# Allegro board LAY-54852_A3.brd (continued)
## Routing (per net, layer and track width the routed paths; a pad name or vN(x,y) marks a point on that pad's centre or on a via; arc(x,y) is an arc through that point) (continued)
FRS_EN: length 14.3
  TOP w0.091: U401.1 v1(36.37,16.38)
  TOP w0.203: v1(25.09,15.95) 25.12,15.95 25.33,16.15 U402.B6
  BOTTOM w0.091: v1(25.09,15.95) 25.09,15.78 26.17,14.7 31.07,14.7 33.6,17.23 35.51,17.23 v1(36.37,16.38)
FT_BMODE_DIR: length 16
  TOP w0.091: U1409.14 v1(18.45,57.25) ; v1(21.46,60) 22.14,60.68 24.49,60.68 25.91,59.26 R1728.1 27.76,59.87 29.1,61.21 U1404.5 29.1,62 U1404.4
  BOTTOM w0.091: v1(18.45,57.25) 18.45,58.23 20.22,60 v1(21.46,60)
FT_BOOT_MODE0: length 7.1
  TOP w0.091: U1409.1 24.26,55.25 26.01,57 27.77,57 28.86,58.09 R1731.1
FT_BOOT_MODE1: length 8.4
  TOP w0.091: v1(27.57,57.37) 26.08,57.37 24.45,55.75 U1409.2 ; v1(29.78,57.24) 29.78,57.25 R1732.1
  BOTTOM w0.091: v1(27.57,57.37) 27.7,57.24 v1(29.78,57.24)
FT_BOOT_MODE2: length 9.2
  TOP w0.091: R1418.1 30.75,58.31 v1(30.75,57.62) ; U1409.3 24.64,56.25 26.14,57.75 27.77,57.75 v1(27.97,57.95)
  BOTTOM w0.091: v1(27.97,57.95) 30.41,57.95 v1(30.75,57.62)
FT_BOOT_MODE3: length 10.1
  TOP w0.091: R1419.1 31.36,58.01 v1(31.36,57.61) ; v1(26.64,58.13) 26.21,58.13 24.84,56.75 U1409.4
  BOTTOM w0.091: v1(26.64,58.13) 26.84,58.33 30.63,58.33 v1(31.36,57.61)
FT_EECLK: length 20
  TOP w0.091: v1(3.79,35.78) 3.25,35.78 1.56,37.47 R1428.2 ; U1706.62 v1(8,24.87)
  BOTTOM w0.091: v1(3.79,35.78) 4.85,34.71 4.85,33.41 7.05,31.2 7.05,25.81 v1(8,24.87)
FT_EECS: length 19.4
  TOP w0.091: v1(5.57,35.63) 4.93,36.26 R1740.2 ; v1(8.53,24.89) 8.53,24.71 8.19,24.37 U1706.63
  BOTTOM w0.091: v1(8.53,24.89) 7.37,26.05 7.37,31.2 5.57,33 v1(5.57,35.63)
FT_EEDATA: length 28
  TOP w0.091: v1(8.58,25.66) 8.29,25.37 U1706.61 ; v1(4.22,47.2) 2.94,47.2 R1739.2
  BOTTOM w0.091: v1(4.22,47.2) 4.9,46.53 4.9,41.95 5.94,40.9 5.94,32.93 7.67,31.21 7.67,26.56 v1(8.58,25.66)
FT_IO_NINT1: length 25.1
  TOP w0.091: v1(18.19,30.39) 18.17,30.37 U1706.30 ; R1487.1 v1(21.61,51.73)
  BOTTOM w0.091: v1(21.61,51.73) 21.61,45.93 18.14,42.46 18.14,37.56 17.5,36.92 17.5,31.09 v1(18.19,30.39)
FT_IOEXP2_SCL: length 4.1
  TOP w0.091: U1409.19 17.94,54.54 16.9,53.5 R1470.2
FT_IOEXP2_SDA: length 4.1
  TOP w0.091: U1409.20 20.46,54.17 20.25,53.97 17.99,53.97 17.81,53.79 17.81,53.2 R1469.2
FT_NPWREN: length 62.9
  TOP w0.091: v1(6.07,62.71) 6.17,62.82 11.01,62.82 12.67,64.47 17.59,64.47 19.04,65.93 R1749.1 ; R1464.1 6.13,49.4 v1(6.13,48.87) ; v1(8.53,26.24) 8.17,25.87 U1706.60 4.53,25.87 3.8,25.14 3.8,24.75 2.1,23.06 TP1407.1
  BOTTOM w0.091: v1(6.07,62.71) 5.33,61.98 5.33,49.66 v1(6.13,48.87) 6.13,46.96 6.67,46.42 6.67,33.48 8.53,31.61 v1(8.53,26.24)
FT_NSUSPEND: length 36.1
  TOP w0.091: R1744.1 v1(13.36,65.81) ; v1(14.51,37.34) 14.51,37.05 TP1408.1 13.5,36.04 U1706.36
  BOTTOM w0.091: v1(13.36,65.81) 13.14,66.03 12.4,66.03 11.87,65.49 11.87,60.46 13.49,58.84 13.49,41.07 14.51,40.04 v1(14.51,37.34)
FT_ONOFF: length 8.6
  TOP w0.091: U1409.12 18.06,58.46 16.91,59.6 16.91,61.49 17.21,61.79 U1406.3 19.25,61.79 R1746.1
FT_OSCI: length 8.9
  TOP w0.091: X1401.1 3.94,18 3.94,19.17 4.52,19.75 4.52,19.84 C1428.1 4.7,20.63 5.03,20.96 7.91,20.96 8,21.05 U1706.2
FT_OSCO: length 6.4
  TOP w0.091: X1401.3 5.39,18.95 C1430.1 5.39,20.61 5.51,20.73 8.1,20.73 8.5,21.13 U1706.3
FT_POR_B: length 13.5
  TOP w0.091: R1747.1 13.94,61.79 U1406.6 16.09,61.79 17.45,63.15 20.77,63.15 21.62,62.3 21.62,61.08 20.96,60.41 U1409.10
FT_RC_SEL: length 15.4
  TOP w0.091: U1409.13 17.73,57.75 16.76,58.73 v1(16.21,58.73) ; v1(15.67,69.68) 15.77,69.79 R1751.1
  BOTTOM w0.091: v1(15.67,69.68) 16.21,69.14 v1(16.21,58.73)
FT_SCL: length 29.4
  TOP w0.091: TP1912.1 19,27.73 18.8,27.92 R1726.1 18.45,28.3 18.38,28.37 v1(18.21,28.37) U1706.26 ; R1470.1 16.9,52.06 v1(17.36,51.6)
  BOTTOM w0.091: v1(17.36,51.6) 17.58,51.38 17.58,38.25 16.43,37.1 16.43,30.15 v1(18.21,28.37)
FT_SD_CD: length 181.7
  TOP w0.091: U1409.16 18.56,56.25 v1(18.5,56.31) ; U1707.1 134.76,42.76 135,43 v1(135,43.69) R1053.2
  BOTTOM w0.091: v1(135,43.69) 134.92,43.69 133.16,45.45 133.16,69.97 133.34,70.15 133.34,76.85 125.88,84.31 21.49,84.31 18.08,80.89 18.08,56.74 v1(18.5,56.31)
FT_SD_PWREN: length 182.5
  TOP w0.091: U1409.15 18.18,56.75 v1(17.64,57.29) ; R1057.1 137.37,44.31 R1056.2 v1(136.15,43.67)
  BOTTOM w0.091: v1(136.15,43.67) 133.38,46.44 133.38,69.88 133.56,70.06 133.56,76.94 125.97,84.53 21.22,84.53 17.57,80.88 17.57,57.36 v1(17.64,57.29)
FT_SDA: length 29.3
  TOP w0.091: v1(18.18,29.37) 18.43,29.37 18.44,29.38 R1727.1 18.79,29.2 19.07,28.92 20.5,28.92 TP1913.1 ; v1(18.18,29.37) 18.18,28.96 18.09,28.87 U1706.27 ; v1(18.18,29.37) U1706.28 ; R1469.1 18.08,51.76 v1(17.9,51.58)
  BOTTOM w0.091: v1(18.18,29.37) 16.96,30.59 16.96,36.69 17.9,37.63 v1(17.9,51.58)
FT_SYS_NRST: length 3.9
  TOP w0.091: U1406.1 19.14,60.79 R1745.1 19.79,59.35 20.46,58.69 U1409.11
FT_TST0: length 43.7
  TOP w0.091: U1706.21 17.84,25.87 v1(18.03,26.05) ; R1455.1 v1(9.3,64.08)
  BOTTOM w0.091: v1(18.03,26.05) 17.74,26.05 15.64,28.15 15.64,33.72 11.65,37.71 11.65,55.89 9.3,58.24 v1(9.3,64.08)
FT_TST1: length 41.1
  TOP w0.091: v1(18.01,26.59) 17.8,26.37 U1706.22 ; v1(24.41,61.31) 24.69,61.59 R1457.1
  BOTTOM w0.091: v1(18.01,26.59) 18.67,27.24 18.67,41.35 23.07,45.76 23.07,59.97 v1(24.41,61.31)
FT_TST2: length 8
  TOP w0.091: R1456.1 17.69,22.87 16.04,22.87 15.64,23.27 15.64,26.46 16.04,26.87 U1706.23
FT_TST3: length 40.7
  TOP w0.091: U1706.24 v1(11.06,27.37) ; R1458.1 6.47,57.8 7.23,57.04 7.23,55.91 5.42,54.1 5.42,52.5 5.73,52.19 5.73,50.84 6.75,49.81 v1(6.75,48.82)
  BOTTOM w0.091: v1(11.06,27.37) 9.36,29.07 9.36,44.68 6.75,47.28 v1(6.75,48.82)
FT_USB_DN: length 16.7
  TOP w0.102: U1403.C1 15.52,9.92 15.52,10.79 15.64,10.91 v1(15.64,10.97) ; U1706.7 10.5,21.01 10.65,20.86 10.65,16.42 14.39,12.68 14.39,12.45 v1(14.39,12.44)
  BOTTOM w0.102: v1(15.64,10.97) 15.64,10.91 15.52,10.79 15.52,10.28 15.17,9.94 14.7,9.94 14.1,10.54 14.1,11.46 14.39,11.76 v1(14.39,12.44)
FT_USB_DP: length 16.6
  TOP w0.102: U1403.C2 15.1,9.93 15.31,10.13 15.31,10.79 v1(15.06,11.03) ; v1(14.95,12.4) 14.95,12.42 10.86,16.51 10.86,20.86 11,21.01 U1706.8
  BOTTOM w0.102: v1(14.95,12.4) 14.89,12.4 14.61,12.12 14.61,11.67 14.31,11.37 14.31,10.63 14.79,10.15 15.08,10.15 15.31,10.37 15.31,10.79 v1(15.06,11.03)
FTA_TCK: length 20.7
  TOP w0.091: v1(16.93,21.86) 16.92,21.84 U1706.16 ; U1408.2 21.85,37.79 21.06,37 21.06,27.27 20.35,26.56 v1(19.94,26.56)
  BOTTOM w0.091: v1(16.93,21.86) 16.93,23.61 19.89,26.56 v1(19.94,26.56)
FTA_TDI: length 17.7
  TOP w0.091: U1706.17 18.82,23.87 20.08,25.13 20.08,25.98 21.28,27.18 21.28,36.65 22.25,37.62 U1408.3
FTA_TDO: length 18.6
  TOP w0.091: U1706.18 v1(18.22,24.37) ; U1408.5 23.05,37.55 21.71,36.22 21.71,27 20.54,25.82 20.54,24.68 v1(19.92,24.06)
  BOTTOM w0.091: v1(18.22,24.37) 19.6,24.37 v1(19.92,24.06)
FTA_TMS: length 22.3
  TOP w0.091: U1706.19 15.96,24.87 15.85,24.76 15.85,23.36 16.13,23.09 18.35,23.09 20.3,25.04 20.3,25.89 21.49,27.09 21.49,36.31 22.65,37.46 U1408.4
FTC_RXD: length 17.5
  TOP w0.091: R1819.1 8.51,44.55 7.98,44.02 7.13,44.02 6.95,43.84 D1404.C 7.98,41.99 7.98,39.6 8.95,38.64 11.72,38.64 12.83,37.53 12.83,35.83 12,35.01 U1706.39
FTC_TXD: length 15.2
  TOP w0.091: R1817.1 11.73,44.27 12.17,44.27 12.58,43.86 D1403.C 11.7,43.37 11.22,42.88 11.22,39.5 13.21,37.51 13.21,35.43 12.5,34.73 U1706.38
FTD_CTS: length 3.5
  TOP w0.091: TP1406.1 2.39,28.87 U1706.54
FTD_RTS: length 3.6
  TOP w0.091: TP1405.1 2.53,29.37 U1706.53
FTD_RXD: length 32.9
  TOP w0.091: U1706.52 7.94,29.87 v1(8.05,29.97) ; R1820.1 6.49,45.3 6.04,44.85 v1(6.04,41.93)
  TOP w0.381: v1(4.23,50.69) 3.1,51.82 3.1,52.43 D1405.C
  BOTTOM w0.091: v1(4.23,50.69) 5.11,49.81 5.11,42.86 v1(6.04,41.93) 6.45,41.52 6.45,33.38 8.05,31.79 v1(8.05,29.97)
FTD_TXD: length 13.6
  TOP w0.091: v1(7.26,34.48) 7.5,34.24 U1706.48 ; v1(8.61,39.63) 8.61,43.15 8.92,43.47 D1406.C 9.73,44.17 9.6,44.3 R1818.1
  BOTTOM w0.091: v1(8.61,39.63) 8.61,35.89 7.26,34.55 v1(7.26,34.48)
GPIO_IO00: length 51.1
  TOP w0.081: 92.71,56.46 92.39,56.46 92.14,56.21 U101.B16
  TOP w0.091: v1(115.92,54.45) 115.77,54.45 115.08,53.75 102.5,53.75 98.58,57.68 93.93,57.68 92.71,56.46 ; R1415.2 v1(120.16,73.59) 120.16,74.11 121.21,75.16 J1401.27
  BOTTOM w0.091: v1(115.92,54.45) 115.92,54.58 118.53,57.19 118.53,69.58 119.67,70.71 119.67,73.1 v1(120.16,73.59)
GPIO_IO01: length 56.8
  TOP w0.091: U101.B17 92.83,56.21 94.09,57.46 98.49,57.46 102.41,53.54 115.54,53.54 v1(115.91,53.9) ; J1401.28 121.21,79.28 122.07,78.41 122.07,74.27 v1(121.52,73.72) 121.35,73.56 R1417.2
  BOTTOM w0.091: v1(121.52,73.72) 120.07,72.28 120.07,70.23 118.75,68.91 118.75,56.75 v1(115.91,53.9)
GPIO_IO02: length 39.5
  TOP w0.081: 92.87,55.96 92.25,55.96 U101.C16
  TOP w0.091: J1401.3 90.73,74.11 90.86,73.97 v1(90.86,73.72) R1414.2 ; 92.87,55.96 93.06,55.96 94.32,57.22 95.52,57.22 96.54,56.2 v1(96.74,56.2)
  BOTTOM w0.091: v1(96.74,56.2) 96.74,56.34 97.49,57.09 97.49,62.5 95.75,64.24 95.75,68.08 93.39,70.44 93.26,70.44 92.45,69.63 92.33,69.63 92.2,69.76 92.2,69.89 93,70.7 93,70.83 92.87,70.96 92.74,70.96 91.94,70.15 91.81,70.15 91.68,70.28 91.68,70.41 92.49,71.22 92.49,71.35 92.36,71.48 92.23,71.48 91.42,70.67 91.29,70.67 91.16,70.8 91.16,70.93 91.97,71.74 91.97,71.87 91.84,71.99 91.71,71.99 90.9,71.19 90.77,71.19 90.64,71.32 90.64,71.45 91.45,72.25 91.45,72.38 90.86,72.97 v1(90.86,73.72)
GPIO_IO03: length 38.7
  TOP w0.091: U101.C17 96.95,55.71 97.27,56.03 v1(97.27,56.19) ; R1416.2 93.27,73.24 v1(93.27,73.72) J1401.5
  BOTTOM w0.091: v1(97.27,56.19) 97.74,56.67 97.74,62.56 96.02,64.28 96.02,68.21 93.37,70.86 93.37,72.35 93.25,72.48 91.8,72.48 91.7,72.57 91.7,72.75 91.8,72.84 94.73,72.84 94.82,72.93 94.82,73.08 94.73,73.17 91.38,73.17 91.24,73.31 91.24,73.97 91.38,74.11 93.18,74.11 93.27,74.02 v1(93.27,73.72)
GPIO_IO04: length 46
  TOP w0.081: U101.D16 92.24,55.45 92.98,55.45
  TOP w0.091: 92.98,55.45 97.19,55.45 97.8,56.07 v1(97.8,56.16) ; v1(90.24,73.79) 87.98,73.79 R1429.1 ; v1(95.1,73.79) 95.81,74.5 J1401.7
  BOTTOM w0.091: v1(97.8,56.16) 97.96,56.32 97.96,62.65 96.32,64.3 96.32,68.22 93.68,70.86 93.68,71.53 93.77,71.62 95.21,71.62 95.3,71.53 95.3,70.47 95.4,70.38 95.65,70.38 95.74,70.47 95.74,71.96 95.65,72.05 93.84,72.05 93.68,72.21 93.68,72.37 93.77,72.46 95.56,72.46 95.65,72.55 95.65,72.79 95.56,72.88 95.26,72.88 95.14,73 95.14,73.2 95.27,73.33 95.56,73.33 95.65,73.42 95.65,73.7 95.56,73.79 v1(95.1,73.79) 94.49,74.4 90.85,74.4 v1(90.24,73.79)
GPIO_IO05: length 50.6
  TOP w0.091: U101.D17 100.43,55.21 102.32,53.32 115.86,53.32 v1(115.88,53.34) ; J1401.29 v1(123.75,74.22)
  BOTTOM w0.091: v1(123.75,74.22) 121.75,72.22 121.75,70.99 118.97,68.21 118.97,56.2 116.11,53.34 v1(115.88,53.34)
GPIO_IO06: length 53.8
  TOP w0.081: 92.63,54.96 92.25,54.96 U101.E16
  TOP w0.091: J1401.31 v1(126.29,74.22) ; 92.63,54.96 100.37,54.96 102.23,53.1 115.53,53.1 115.82,52.81 v1(115.94,52.81)
  BOTTOM w0.091: v1(115.94,52.81) 116.1,52.81 119.19,55.9 119.19,68.11 122.06,70.98 122.06,71.52 124.75,74.22 v1(126.29,74.22)
GPIO_IO07: length 55.1
  TOP w0.091: v1(115.92,52.21) 115.25,52.88 102.14,52.88 100.32,54.71 U101.E17 ; J1401.26 v1(118.67,79.17)
  BOTTOM w0.091: v1(115.92,52.21) 115.92,52.3 115.5,52.72 115.5,54.61 118.32,57.42 118.32,63.71 118.21,63.81 118.21,74.29 118.67,74.75 v1(118.67,79.17)
GPIO_IO08: length 49.4
  TOP w0.081: U101.K14 v1(90.99,51.71)
  TOP w0.091: v1(97.08,61.6) 103.39,55.29 105.11,55.29 105.75,55.94 106.28,55.94 106.52,55.7 107.41,55.7 107.8,56.09 v1(108.6,56.09)
  TOP w0.102: v1(110.62,73.04) 111.04,72.63 U805.2
  BOTTOM w0.091: v1(110.62,73.04) 109.64,73.04 107.72,71.13 107.72,67.1 108.07,66.75 108.07,57.34 108.6,56.81 v1(108.6,56.09) ; v1(97.08,61.6) 96.62,61.13 96.62,56.92 95.99,56.29 95.99,55.26 92.07,51.35 91.11,51.35 90.99,51.46 v1(90.99,51.71)
GPIO_IO09: length 40.1
  TOP w0.081: U101.F16 92.24,54.45 92.88,54.45
  TOP w0.091: 92.88,54.45 100.26,54.45 102.21,52.5 v1(109.21,52.5)
  TOP w0.102: U805.5 v1(109.63,72.13)
  BOTTOM w0.091: v1(109.21,52.5) 109.61,52.9 109.61,58.47 108.34,59.74 108.34,66.8 107.94,67.19 107.94,70.98 109.08,72.13 v1(109.63,72.13)
GPIO_IO10: length 38.3
  TOP w0.091: U101.F17 100.2,54.21 102.28,52.12 109.36,52.12 109.73,52.49 v1(109.74,52.49)
  TOP w0.102: U805.7 v1(109,70.81)
  BOTTOM w0.091: v1(109.74,52.49) 109.82,52.58 109.82,59.17 109.37,59.62 109.37,66.14 108.16,67.36 108.16,69.97 v1(109,70.81)
GPIO_IO11: length 40.6
  TOP w0.081: U101.G16 92.24,53.95 92.79,53.95
  TOP w0.091: v1(110.27,52.49) 110.27,52.49 109.68,51.9 102.19,51.9 100.14,53.95 92.79,53.95
  TOP w0.102: U805.10 110.64,69.6 110.19,69.14 109.3,69.14 v1(108.97,69.48)
  BOTTOM w0.091: v1(108.97,69.48) 108.59,69.48 108.38,69.27 108.38,67.53 110.37,65.54 110.37,59.04 110.04,58.72 110.04,53.06 110.27,52.83 v1(110.27,52.49)
GPIO_IO12: length 61.6
  TOP w0.081: U101.F14 v1(90.99,53.71)
  TOP w0.091: U803.2 133.17,71.1 133.59,70.68 133.59,67.24 130.53,64.17 125.52,64.17 123.41,62.06 119.18,62.06 115.8,58.67 115.8,57.63 113.23,55.07 103.31,55.07 97.21,61.17 95.39,61.17 v1(95.33,61.1)
  BOTTOM w0.081: 92.13,54.87 92.13,55.64 93.35,56.87 93.35,58.33
  BOTTOM w0.091: 93.35,58.33 93.51,58.48 93.51,59.74 94.87,61.1 v1(95.33,61.1) ; 92.13,54.87 90.99,53.74 v1(90.99,53.71)
GPIO_IO13: length 126.8
  TOP w0.091: v1(104.68,82.94) 104.68,84.14 104.89,84.35 126.71,84.35 127.7,83.35 127.7,78.89 128.83,77.77 J1401.33 128.83,74.36 129.21,73.99 129.21,70.22 v1(128.83,69.85) ; v1(127.11,60.33) 126.9,60.12 119.25,60.12 117.3,58.17 117.3,53.03 115.95,51.69 102.1,51.69 100.05,53.73 92.52,53.73 U101.G17 ; v1(77.71,82.63) 77.71,76.85 76,75.14 R1439.1
  BOTTOM w0.091: v1(128.83,69.85) 128.83,62.96 127.11,61.24 v1(127.11,60.33) ; v1(77.71,82.63) 78.03,82.94 v1(104.68,82.94)
GPIO_IO14: length 43.9
  TOP w0.081: U101.H16 92.25,53.46 92.74,53.46
  TOP w0.091: J1401.8 95.81,79.2 96.67,78.34 96.67,73.73 v1(97.08,73.32) ; v1(97.53,52.84) 96.78,52.84 96.15,53.46 92.74,53.46
  BOTTOM w0.091: v1(97.08,73.32) 96.23,73.32 96.05,73.13 96.05,70.34 97.74,68.64 97.74,66.96 97.65,66.87 96.86,66.87 96.77,66.78 96.77,66.59 96.86,66.5 97.65,66.5 97.74,66.41 97.74,66.23 97.65,66.14 96.86,66.14 96.77,66.05 96.77,65.86 96.86,65.77 97.65,65.77 97.74,65.68 97.74,65.5 97.65,65.41 96.86,65.41 96.77,65.31 96.77,65.13 96.86,65.04 97.65,65.04 97.74,64.95 97.74,64.77 97.65,64.67 96.86,64.67 96.77,64.58 96.77,64.4 96.86,64.31 97.65,64.31 97.74,64.22 97.74,63.47 98.18,63.04 98.18,53.49 v1(97.53,52.84)
GPIO_IO15: length 40.9
  TOP w0.091: U101.H17 96.1,53.21 97,52.3 v1(97.57,52.3) ; v1(97.79,73.27) 98.52,73.27 99.24,73.98 99.24,79.31 98.35,80.2 J1401.10
  BOTTOM w0.091: v1(97.79,73.27) 97.47,72.95 97.47,71.63 98.43,70.67 98.43,70.16 98.34,70.07 98.16,70.07 98.07,69.98 98.07,69.8 98.16,69.71 98.34,69.71 98.43,69.62 98.43,69.43 98.34,69.34 98.16,69.34 98.07,69.25 98.07,69.07 98.16,68.98 98.34,68.98 98.43,68.88 98.43,68.7 98.34,68.61 98.16,68.61 98.07,68.52 98.07,68.34 98.16,68.24 98.34,68.24 98.43,68.15 98.43,67.97 98.34,67.88 98.16,67.88 98.07,67.79 98.07,67.6 98.16,67.51 98.34,67.51 98.43,67.42 98.43,67.24 98.34,67.15 98.16,67.15 98.07,67.06 98.07,66.87 98.16,66.78 98.34,66.78 98.43,66.69 98.43,66.51 98.34,66.42 98.16,66.42 98.07,66.32 98.07,66.14 98.16,66.05 98.34,66.05 98.43,65.96 98.43,65.78 98.34,65.68 98.16,65.68 98.07,65.59 98.07,65.41 98.16,65.32 98.34,65.32 98.43,65.23 98.43,65.04 98.34,64.95 98.16,64.95 98.07,64.86 98.07,64.68 98.16,64.59 98.34,64.59 98.43,64.5 98.43,53.04 97.69,52.3 v1(97.57,52.3)
GPIO_IO16: length 38.5
  TOP w0.081: U101.J16 92.25,52.96 92.79,52.96
  TOP w0.091: U804.2 101.09,72.63 101.78,73.32 101.78,73.91 v1(101.58,74.11) ; 92.79,52.96 96.04,52.96 97.07,51.93 101.32,51.93 v1(101.41,51.84)
  BOTTOM w0.091: v1(101.58,74.11) 101.48,74.11 101.13,74.46 100.16,74.46 100.06,74.36 100.06,74.15 100.19,74.03 100.69,74.03 100.77,73.95 100.77,73.56 100.68,73.47 100.14,73.47 100.05,73.38 100.05,73.2 100.14,73.11 100.68,73.11 100.77,73.01 100.77,52.4 101.33,51.84 v1(101.41,51.84)
GPIO_IO17: length 38.3
  TOP w0.081: 92.7,52.45 91.74,52.45 U101.K15
  TOP w0.091: U804.5 99.53,72.13 v1(99.18,72.48) ; v1(98.02,51.33) 97.04,51.33 95.92,52.45 92.7,52.45
  BOTTOM w0.091: v1(99.18,72.48) 99.02,72.48 98.62,72.08 98.62,71.21 99.36,70.47 99.74,70.47 99.83,70.38 99.83,70.19 99.74,70.1 99.36,70.1 99.27,70.01 99.27,69.83 99.36,69.74 99.74,69.74 99.83,69.64 99.83,69.46 99.74,69.37 99.36,69.37 99.27,69.28 99.27,69.1 99.36,69 99.74,69 99.83,68.91 99.83,68.73 99.74,68.64 99.36,68.64 99.27,68.55 99.27,68.36 99.36,68.27 99.74,68.27 99.83,68.18 99.83,68 99.74,67.91 99.36,67.91 99.27,67.82 99.27,67.63 99.36,67.54 99.74,67.54 99.83,67.45 99.83,67.27 99.74,67.18 99.36,67.18 99.27,67.08 99.27,66.9 99.36,66.81 99.74,66.81 99.83,66.72 99.83,66.54 99.74,66.44 99.36,66.44 99.27,66.35 99.27,66.17 99.36,66.08 99.74,66.08 99.83,65.99 99.83,65.8 99.74,65.71 99.36,65.71 99.27,65.62 99.27,65.44 99.36,65.35 99.74,65.35 99.83,65.26 99.83,65.07 99.74,64.98 99.36,64.98 99.27,64.89 99.27,64.71 99.36,64.62 99.74,64.62 99.83,64.52 99.83,64.34 99.74,64.25 99.36,64.25 99.27,64.16 99.27,52.58 v1(98.02,51.33)
GPIO_IO18: length 63.2
  TOP w0.081: U101.M14 v1(90.99,50.76)
  TOP w0.091: v1(97.12,59.28) 98.78,59.28 103.22,54.85 113.32,54.85 116.02,57.54 116.02,58.58 119.16,61.72 123.38,61.72 125.61,63.95 130.62,63.95 133.81,67.15 133.81,71.6 132.9,72.51 U803.5
  BOTTOM w0.091: v1(97.12,59.28) 96.89,59.05 96.89,56.88 96.2,56.2 96.2,55.07 92.3,51.16 91.17,51.16 90.99,50.98 v1(90.99,50.76)
GPIO_IO19: length 61.4
  TOP w0.091: U803.7 v1(131.02,73.21) ; U101.J17 95.98,52.71 96.98,51.71 100.06,51.71 100.3,51.47 116.04,51.47 117.53,52.96 117.53,58.04 119.35,59.86 v1(132.11,59.86)
  BOTTOM w0.091: v1(132.11,59.86) 132.46,60.21 132.46,68.97 131.02,70.42 v1(131.02,73.21)
GPIO_IO20: length 61.4
  TOP w0.081: 92.77,51.96 92.24,51.96 U101.K16
  TOP w0.091: 92.77,51.96 95.8,51.96 97.02,50.74 116.69,50.74 117.75,51.8 117.75,57.95 119.44,59.64 131.2,59.64 v1(131.36,59.48) ; v1(129.81,71.66) 129.97,71.5 U803.10
  BOTTOM w0.091: v1(131.36,59.48) 131.36,60.43 132.03,61.1 132.03,68.79 130.38,70.44 130.38,71.1 v1(129.81,71.66)
GPIO_IO21: length 38.1
  TOP w0.091: U101.K17 95.86,52.21 97.11,50.96 98.21,50.96 v1(98.55,51.29) ; U804.7 v1(99.03,71.33)
  BOTTOM w0.091: v1(99.03,71.33) 99.77,71.33 100.05,71.04 100.05,62.25 99.96,62.16 99.58,62.16 99.49,62.07 99.49,61.89 99.58,61.8 99.96,61.8 100.05,61.71 100.05,61.52 99.96,61.43 99.58,61.43 99.49,61.34 99.49,61.16 99.58,61.07 99.96,61.07 100.05,60.97 100.05,60.79 99.96,60.7 99.58,60.7 99.49,60.61 99.49,60.43 99.58,60.33 99.96,60.33 100.05,60.24 100.05,60.06 99.96,59.97 99.58,59.97 99.49,59.88 99.49,59.69 99.58,59.6 99.96,59.6 100.05,59.51 100.05,59.33 99.96,59.24 99.58,59.24 99.49,59.15 99.49,58.96 99.58,58.87 99.96,58.87 100.05,58.78 100.05,58.6 99.96,58.51 99.58,58.51 99.49,58.41 99.49,58.23 99.58,58.14 99.96,58.14 100.05,58.05 100.05,57.87 99.96,57.77 99.58,57.77 99.49,57.68 99.49,57.5 99.58,57.41 99.96,57.41 100.05,57.32 100.05,57.13 99.96,57.04 99.58,57.04 99.49,56.95 99.49,56.77 99.58,56.68 99.96,56.68 100.05,56.59 100.05,56.4 99.96,56.31 99.58,56.31 99.49,56.22 99.49,56.04 99.58,55.95 99.96,55.95 100.05,55.85 100.05,55.67 99.96,55.58 99.58,55.58 99.49,55.49 99.49,55.31 99.58,55.21 99.96,55.21 100.05,55.12 100.05,52.8 v1(98.55,51.29)
HP_DET: length 54.9
  TOP w0.091: v1(110.42,56.07) 110.42,56.39 R812.2 ; R1822.1 98.4,19.69 96.19,21.9 96.19,30.22 100.86,34.89 109.2,34.89 113.69,39.38 113.69,39.62 v1(113.71,39.64)
  BOTTOM w0.091: v1(110.42,56.07) 110.42,53.23 110.84,52.81 110.84,50.36 113.58,47.63 113.58,39.77 v1(113.71,39.64)
HP_J_D: length 10.7
  TOP w0.203: R1822.2 99.54,15.56 R1202.2 99.54,15.34 TVS1203.2 100.51,13.64 100.07,13.2 99.15,13.2 98.44,12.49 98.44,9.71 J1201.5
HP_J_L: length 6.2
  TOP w0.203: J1201.4 101.79,13.53 TVS1202.2 102.01,14.59 C1771.1 L1202.2
HP_J_R: length 5.7
  TOP w0.203: L1203.2 106.13,15.72 C1772.1 106.04,14.57 TVS1204.2 106.23,12.12 J1201.3
HP_MICIN: length 41.9
  TOP w0.203: J1201.1 106.01,4.99 108.1,7.08 108.1,13.04 107.5,13.64 TVS1201.2 107.5,15.86 R1809.2 107.74,16.22 v1(107.02,16.94) ; C1788.2 99.64,32.77 96.79,29.93 96.79,22.15 100.48,18.46 v1(100.48,17.76)
  BOTTOM w0.203: v1(100.48,17.76) 101.15,17.09 106.87,17.09 v1(107.02,16.94)
HPOUTL: length 10.1
  TOP w0.076: U1709.B5 103.27,26.57 103.27,25.82
  TOP w0.203: 103.27,25.82 103.25,25.81 103.25,21 103.34,20.91 C1769.1 103.34,18.16 R1823.1 103.39,18.11 L1202.1
HPOUTR: length 10
  TOP w0.076: U1709.A5 103.54,26.31 103.54,25.29
  TOP w0.203: L1203.1 104.75,18.05 R1810.1 104.75,19 C1770.1 104.7,20.1 103.64,21.16 103.64,25.19 103.54,25.29
I2C1_SCL: length 211.2
  TOP w0.091: v1(113.89,30.94) 113.78,31.05 112.63,31.05 112.17,31.5 112.17,32.41 111.17,33.41 109.61,33.41 109.35,33.16 109.35,32.14 v1(108.68,31.47) 108.65,31.51 R1212.1 ; U101.A12 89.99,58.69 93.19,61.89 93.19,65.19 v1(92.64,65.74) 90.63,67.75 66.51,67.75 v1(66.22,68.04) ; R717.1 68.98,23.66 68.88,23.55 68.88,21.4 v1(69.03,21.25) 69.11,21.17 69.11,19.49 67.08,17.47 64.43,17.47 63,16.04 63,13.26 R1008.1 ; v1(93.58,69.72) 93.77,69.54 v1(103.09,69.54) 108,69.54 108.66,68.88 115.59,68.88 v1(116.06,68.41) R163.2 ; R1443.1 v1(65.51,72.31) ; R828.1 103.27,62.26 R307.2 v1(103.21,61.49)
  BOTTOM w0.081: 101.42,30.67 101.46,30.71
  BOTTOM w0.091: v1(103.21,61.49) 103.11,61.59 103.11,69.51 v1(103.09,69.54) ; v1(66.22,68.04) 66.22,71.6 v1(65.51,72.31) ; v1(116.06,68.41) 115.74,68.09 115.74,66.27 117.08,64.93 117.08,58.44 114.92,56.28 114.92,52.13 118.17,48.88 118.17,43.82 119.85,42.15 119.85,37.8 121.91,35.73 121.91,34.18 120.46,32.73 110.84,32.73 109.59,31.47 v1(108.68,31.47) 102.23,31.47 101.46,30.71 ; v1(69.03,21.25) 69.49,20.78 70.5,20.78 71.36,21.64 77.68,21.64 77.9,21.86 92.5,21.86 101.31,30.67 101.42,30.67 ; v1(113.89,30.94) 114.47,30.36 114.47,28.61 113.77,27.91 113.19,27.91 112.28,27 112.28,25.15 R433.1 ; v1(92.64,65.74) 93.58,66.68 v1(93.58,69.72)
I2C1_SCLL: length 57.8
  TOP w0.091: J1707.60 118.6,15.4 117.11,16.9 v1(117.11,17.81) R930.2 ; R713.2 71.18,22.86 71.77,22.86 R65.1 73.24,21.39 73.24,17.81 v1(73.3,17.75)
  BOTTOM w0.091: v1(117.11,17.81) 117.05,17.81 116.88,17.97 114.23,17.97 113.13,19.08 77.8,19.08 76.3,17.58 74.13,17.58 73.95,17.75 v1(73.3,17.75)
I2C1_SDA: length 198.9
  TOP w0.081: 90.25,56.95 90.25,56.46 U101.B12
  TOP w0.091: R164.2 v1(116.25,62.85) ; v1(113.84,30.36) 113.84,28.7 112.63,27.49 110.72,27.49 110.34,27.88 110.34,29.53 110.06,29.81 108.87,29.81 R1211.1 108.59,30.97 109.47,30.97 109.71,31.21 109.71,32.75 v1(109.81,32.85) ; R830.1 103.31,57.98 R306.2 103.21,57.57 v1(102.96,57.32) 102.29,57.32 101.8,57.82 101.8,59.76 96.84,64.71 96.84,65.09 v1(95.32,66.61) ; R1009.1 63.97,15.54 65.22,16.79 67.88,16.79 70.38,19.29 70.38,21.52 v1(70.27,21.62) ; v1(106.02,55.55) 106.29,55.28 107.45,55.28 108,55.84 108.28,55.84 108.45,55.66 113,55.66 114.33,56.99 v1(114.33,57.08) ; v1(68.14,68.13) 68.25,68.13 68.41,67.97 90.95,67.97 93.57,65.35 v1(93.57,64.76) 93.57,61.95 90.25,58.63 90.25,56.95 ; v1(67.84,21.63) 67.84,22.44 68.27,22.87 R719.1 ; v1(68.14,72.31) 67.46,72.31 R1445.1
  BOTTOM w0.091: v1(102.96,57.32) 104.25,57.32 106.02,55.55 v1(106.02,55.55) ; v1(113.84,30.36) 114.25,29.95 114.25,28.72 113.69,28.15 113.07,28.15 112.06,27.14 112.06,24.41 R432.1 ; v1(68.14,68.13) v1(68.14,72.31) ; v1(67.84,21.63) 67.84,21.62 v1(70.27,21.62) 70.73,22.07 76.75,22.07 77.13,22.46 91.65,22.46 102.06,32.87 109.35,32.87 109.38,32.85 v1(109.81,32.85) 109.84,32.88 109.84,32.96 110.26,33.38 120.18,33.38 121.12,34.31 121.12,35.6 119.19,37.52 119.19,41.82 117.48,43.54 117.48,48.64 114.26,51.86 114.26,56.93 114.33,56.99 v1(114.33,57.08) 114.41,57.08 116.41,59.07 116.41,62.69 v1(116.25,62.85) ; v1(93.57,64.76) 93.57,64.85 v1(95.32,66.61)
I2C1_SDAL: length 60.9
  TOP w0.091: R712.2 69.7,23.16 70.34,22.51 71.14,22.51 R64.1 70.88,21.09 v1(70.88,18.08) ; R931.2 v1(118.13,17.74) 118.13,16.42 119.1,15.44 J1707.58
  BOTTOM w0.091: v1(70.88,18.08) 70.93,18.13 74.38,18.13 74.71,17.8 76.21,17.8 77.71,19.29 113.22,19.29 114.32,18.19 117.68,18.19 v1(118.13,17.74)
I2C2_SCL: length 111.5
  TOP w0.091: v1(52.78,45.04) 53.55,44.27 71.35,44.27 73.18,42.44 73.18,38.67 R714.1 ; v1(53.65,62.02) 60.41,62.02 65.7,67.31 90.13,67.31 92.31,65.13 v1(92.31,65.01) 92.31,64.73 92.76,64.29 92.76,62.07 89.49,58.81 U101.A11 ; v1(94.8,67.99) 95.66,67.99 98.22,65.44 102.51,65.44 103.18,64.77 103.18,63.4 R309.2 103.26,63.33 R820.1
  BOTTOM w0.091: v1(92.31,65.01) 92.44,65.01 94.8,67.37 v1(94.8,67.99) ; v1(53.65,62.02) 53.65,60.2 52.21,58.76 52.21,45.61 v1(52.78,45.04)
I2C2_SDA: length 112.2
  TOP w0.081: U101.B11 89.75,56.46 89.75,56.96
  TOP w0.091: v1(94.95,66.99) 95.02,66.99 95.06,67.02 95.44,67.02 97.23,65.23 97.23,64.63 100.96,60.9 102,60.9 103.21,59.7 R308.2 103.24,59.05 R824.1 ; v1(53.11,62.05) 53.45,62.39 60.48,62.39 65.61,67.53 90.32,67.53 92.82,65.04 v1(92.82,64.76) 92.97,64.6 92.97,61.98 89.75,58.75 89.75,56.96 ; v1(52.14,45.12) 52.14,44.91 52.99,44.05 71.26,44.05 72.78,42.54 R715.1
  BOTTOM w0.091: v1(53.11,62.05) 53.11,60.1 51.99,58.98 51.99,45.27 v1(52.14,45.12) ; v1(94.95,66.99) 94.95,66.91 92.82,64.78 v1(92.82,64.76)
I2C3_SCL: length 121.7
  TOP w0.091: R1405.2 122.41,72.31 R1417.1 120.89,71.84 118.34,71.84 118.28,71.79 117.92,71.79 v1(117.44,71.3) ; R1413.1 116.14,67.29 v1(116.13,67.29) ; v1(68.68,20.84) 68.68,19.51 66.86,17.69 64.17,17.69 62.67,16.19 62.67,12.47 R1015.1
  BOTTOM w0.091: v1(117.44,71.3) 117.44,69.21 116.13,67.9 v1(116.13,67.29) 116.13,66.32 117.44,65.02 117.44,58.42 115.14,56.12 115.14,52.22 118.45,48.91 118.45,43.95 120.07,42.34 120.07,38.2 122.24,36.03 122.24,34.21 120.55,32.51 110.93,32.51 109.52,31.1 102.16,31.1 92.7,21.64 78.13,21.64 77.91,21.42 71.53,21.42 70.67,20.56 68.91,20.56 68.68,20.8 v1(68.68,20.84)
I2C3_SDA: length 114.4
  TOP w0.091: v1(69.81,21.16) 69.86,21.12 69.86,19.22 67.67,17.03 64.83,17.03 63.56,15.77 63.56,14.8 R1016.1 ; v1(116.23,63.91) 116.34,64.02 116.34,64.02 R1411.1 ; R1415.1 119.07,72.31 R1406.2 117.97,72.36 v1(117.45,71.84)
  BOTTOM w0.091: v1(117.45,71.84) 117.01,71.4 117.01,69.89 115.43,68.31 115.43,64.7 v1(116.23,63.91) 116.63,63.51 116.63,58.61 114.48,56.46 114.48,51.95 117.7,48.73 117.7,43.63 119.41,41.92 119.41,37.61 121.34,35.69 121.34,34.22 120.27,33.16 110.66,33.16 109.6,32.11 101.66,32.11 91.78,22.24 77.69,22.24 77.31,21.86 71.04,21.86 70.43,21.25 69.9,21.25 v1(69.81,21.16)
I2C4_SCL: length 117.8
  TOP w0.091: v1(68.4,22.44) 68.3,22.35 68.3,19.58 66.7,17.98 63.93,17.98 62.39,16.44 62.39,11.69 R1017.1 ; R1416.1 93.51,72.36 R1407.2 97.77,72.36 v1(98.15,72.74)
  BOTTOM w0.091: v1(68.4,22.44) 68.56,22.28 69.41,22.28 70.02,22.89 73.81,22.89 74.5,23.57 76.53,23.57 77.13,24.17 92.08,24.17 102.57,34.66 109.51,34.66 111.8,36.95 111.8,46.35 106.8,51.35 100.71,51.35 100.49,51.58 100.49,72.02 99.42,73.08 98.49,73.08 v1(98.15,72.74)
I2C4_SDA: length 115.6
  TOP w0.091: R1414.1 90.92,72.36 R1408.2 92.62,71.79 97.72,71.79 v1(97.96,72.03) ; v1(69.25,22.65) 69.35,22.65 69.44,22.56 69.44,19.36 67.33,17.25 64.66,17.25 63.28,15.87 63.28,14.14 R1018.1
  BOTTOM w0.091: v1(69.25,22.65) 69.7,23.11 73.62,23.11 74.42,23.9 76.56,23.9 77.04,24.38 91.95,24.38 102.44,34.87 109.35,34.87 111.58,37.11 111.58,46.26 106.71,51.13 100.62,51.13 100.27,51.49 100.27,71.92 99.32,72.87 98.81,72.87 97.97,72.03 v1(97.96,72.03)
I3C1_SCL: length 16
  TOP w0.091: U1401.13 117.48,67.23 R1413.2 117.41,67.3 R163.1 117.73,68.41 117.88,68.56 117.88,69.11 R1404.2 116.89,69.02 116.07,69.02 115.81,69.28 115.81,72.09 v1(116.07,72.35)
  BOTTOM w0.091: v1(116.07,72.35) 113.77,74.64 R861.1
I3C1_SDA: length 17.5
  TOP w0.091: R1401.2 118.36,66.19 118.9,66.73 U1401.14 ; R1401.2 117.43,66.65 117.28,66.8 114.88,66.8 v1(114.79,66.88) ; R1401.2 117.43,65.74 117.52,65.65 R1403.2 117.43,65.21 R1411.2 117.46,64.34 R164.1
  BOTTOM w0.091: v1(114.79,66.88) 114.68,67 114.68,70.41 116.45,72.19 116.45,74.18 R862.1
I3C_PUR: length 1.2
  TOP w0.091: R1401.1 115.47,66.19 TP1401.1
I3C_TEMP_NINT: length 37.6
  TOP w0.091: v1(116.02,29.03) 115.9,29.16 115.9,37.08 116.08,37.26 v1(116.08,43.03)
  BOTTOM w0.091: R744.2 115.02,28.03 v1(116.02,29.03) ; R860.2 114.79,62.6 114.79,59.5 113.08,57.79 113.08,51.4 116.2,48.28 116.2,43.34 116.08,43.23 v1(116.08,43.03)
I.MX_SPI_CLK/UART_RTSO: length 3
  TOP w0.091: R944.2 122.88,27.15 v1(122.57,27.45) 122.15,27.87 U906.4
  BOTTOM w0.091: U905.8 122.16,27.87 v1(122.57,27.45)
I.MX_SPI_CS/UART_TXD: length 3.8
  TOP w0.091: R938.2 120.7,27 v1(121.08,27.39) 121.35,27.66 U906.2
  BOTTOM w0.091: U905.10 121.36,27.67 v1(121.08,27.39) 120.69,27 R945.2
I.MX_SPI_MISO/UART_RXD: length 3.6
  TOP w0.091: R943.2 123.99,27.69 123.75,27.92 v1(123.3,27.92) 122.9,28.32 U906.5
  BOTTOM w0.091: v1(123.3,27.92) 122.9,28.33 U905.7
I.MX_SPI_MOSI/UART_CTSI: length 3.3
  TOP w0.091: U906.3 121.75,27.44 v1(121.76,27.43) 121.79,27.4 R942.2
  BOTTOM w0.091: U905.9 v1(121.76,27.43) 121.76,26.69 R941.2
ILIM_5V_VBUS: length 2.5
  TOP w0.091: TP1927.1 38.97,16.32 U401.6
IMU_INT1: length 58.9
  TOP w0.091: U804.9 100.29,70.18 100.38,70.08 105.72,70.08 106.85,71.22 106.85,71.44 107.27,71.86 107.27,82.99 108.04,83.76 124.63,83.76 124.92,83.47 124.92,74.06 125.55,73.43 127.51,73.43 128.01,72.93 128.01,65.32 D1401.A
IN1R: length 4.6
  TOP w0.076: U1709.D4 103.77,28.07 102.85,28.07 102.78,28.15 102.78,28.42 102.62,28.57 102.23,28.57
  TOP w0.203: C1787.2 100.58,30.04 102.05,28.57 102.23,28.57
IN3R: length 3.9
  TOP w0.076: U1709.F6 102.77,29.07 102.34,29.07
  TOP w0.203: C1788.1 101.59,30.48 101.59,29.82 102.34,29.07
IOEXP_IO24: length 2.8
  TOP w0.091: J1401.18 v1(108.51,79.17)
  BOTTOM w0.091: v1(108.51,79.17) 108.47,79.21 R851.2
IOEXP_IO25: length 2.8
  TOP w0.091: J1401.22 v1(113.59,79.17)
  BOTTOM w0.091: R850.2 113.57,79.19 v1(113.59,79.17)
IOEXP_IO27: length 26.1
  TOP w0.091: J1401.13 v1(103.43,78.54)
  BOTTOM w0.091: v1(103.43,78.54) 107.46,74.51 111.07,74.51 113.91,71.67 113.91,67.76 113.46,67.31 R852.2
JTAG_TCK: length 86.1
  TOP w0.091: v1(24.6,38.5) 25.76,38.5 29.48,42.22 J1704.4 29.48,45.4 30,45.93 32.76,45.93 33.74,46.9 43.14,46.9 44.24,48.01 47.17,48.01 49.07,49.91 49.53,49.91 51.42,51.8 v1(53.6,51.8) ; TP1922.1 83.75,43.38 R405.1 82.42,42.99 R416.1 82.41,43.66 v1(82.51,43.76) ; v1(81.26,43.77) 81.15,43.88 81.15,44.14 80.82,44.46 73.06,44.46 72.37,45.15 54.85,45.15 53.41,46.58 v1(53.41,46.68) ; U101.U3 85.49,47.72 ; U1408.10 v1(21.85,40.42)
  TOP w0.102: 85.49,47.72 85.49,47.62 84.5,46.63 84.5,45.03 TP1922.1
  BOTTOM w0.091: v1(24.6,38.5) 24.16,38.06 23.11,38.06 21.85,39.32 v1(21.85,40.42) ; v1(53.41,46.68) 53.92,47.18 53.92,51.49 v1(53.6,51.8) ; v1(82.51,43.76) 82.35,43.93 81.42,43.93 v1(81.26,43.77)
JTAG_TDI: length 172.7
  TOP w0.081: U101.P8 v1(87.49,50.21)
  TOP w0.091: v1(52.88,46.62) 52.88,46.36 54.31,44.93 72.28,44.93 72.97,44.24 80.28,44.24 v1(80.57,43.95) ; v1(129.1,19.63) TP1920.1 128.37,19.04 128.46,18.96 R417.1 ; v1(53.12,52.92) 51.93,52.92 49.39,50.39 48.94,50.39 46.99,48.45 44.06,48.45 42.96,47.34 33.56,47.34 32.58,46.36 27.86,46.36 26.94,45.44 J1704.8 26.94,41.83 R1460.2 26.48,41.78 26.07,41.37 26.07,40.82 25.88,40.63 23.86,40.63 23.63,40.85 22.36,40.85 22.25,40.74 U1408.9
  TOP w0.102: v1(76.52,19) 77.01,19.49 77.01,23.76 78.36,25.11 78.36,33.55 79.1,34.29 79.1,36.29 85.2,42.39 85.2,45.93 85.37,46.1 v1(85.58,46.1)
  BOTTOM w0.081: 87.04,49.75 86.22,48.93 86.22,47.56
  BOTTOM w0.091: v1(80.57,43.95) 80.76,44.14 82.14,44.14 84.1,46.1 v1(85.58,46.1) ; v1(129.1,19.63) 128.63,19.16 124.24,19.16 123.53,19.87 119.99,19.87 119.62,19.51 77.03,19.51 v1(76.52,19) ; v1(53.12,52.92) 52.72,52.52 52.72,46.77 v1(52.88,46.62) ; v1(87.49,50.21) 87.04,49.75 ; 86.22,47.56 86.22,46.61
  BOTTOM w0.102: v1(85.58,46.1) 85.71,46.1 86.22,46.61
JTAG_TDO: length 81
  TOP w0.081: 85.25,48.41 85.25,48.96 U101.T3
  TOP w0.091: TP1923.1 82.51,44.26 82.89,44.64 82.89,44.9 83.87,45.88 83.87,46.42 ; TP1923.1 81.97,43.55 R414.1 ; TP1923.1 81.97,44.59 81.67,44.9 73.24,44.9 72.55,45.58 55.75,45.58 v1(53.1,48.24) ; 85.25,48.41 85.25,48.07 ; U1408.7 26.65,39.69 28.21,41.26 J1704.6 28.21,45.42 28.94,46.14 32.67,46.14 33.65,47.12 43.05,47.12 44.15,48.23 47.08,48.23 49.03,50.17 49.49,50.17 51.71,52.39 v1(53.17,52.39)
  TOP w0.102: 83.87,46.42 85.25,47.8 85.25,48.07
  BOTTOM w0.091: v1(53.1,48.24) 53.08,48.25 53.08,52.3 v1(53.17,52.39)
JTAG_TMS: length 165.5
  TOP w0.081: U101.P6 v1(86.47,50.21)
  TOP w0.091: v1(53.12,47.63) 55.39,45.36 72.46,45.36 73.15,44.68 81.25,44.68 v1(81.41,44.52) ; U1408.8 v1(22.65,40.39) ; v1(53.54,51.17) 51.1,51.17 49.61,49.67 49.23,49.67 46.96,47.41 43.95,47.41 43.23,46.69 34.63,46.69 32.29,44.36 J1704.2 30.75,41.66 R1459.2 29.22,41.65 25.7,38.12 24.18,38.12 v1(23.86,38.45) ; TP1921.1 124.88,19.85 v1(124.56,19.53) 124.56,19.12 R419.1
  TOP w0.102: v1(75.97,19.05) 75.97,19.16 76.78,19.98 76.78,23.85 78.13,25.2 78.13,33.64 78.87,34.38 78.87,36.38 84.97,42.49 84.97,46.14 85.46,46.63 v1(85.6,46.63)
  BOTTOM w0.091: v1(75.97,19.05) 76.65,19.73 119.53,19.73 119.89,20.09 124,20.09 v1(124.56,19.53) ; v1(22.65,40.39) 22.65,39.21 23.47,38.39 23.8,38.39 v1(23.86,38.45) ; v1(53.54,51.17) 53.54,48.05 v1(53.12,47.63) ; v1(85.6,46.63) 85.44,46.47 84.1,46.47 82.15,44.52 v1(81.41,44.52)
  BOTTOM w0.102: v1(85.6,46.63) 85.89,46.92 85.89,49.6 86.47,50.18 v1(86.47,50.21)
LD_I2C_SCL: length 24.3
  TOP w0.091: R420.1 41.03,19.75 41.15,19.87 42.04,19.87 42.96,18.95 42.96,15.01 42.22,14.27 38.82,14.27 37.57,13.01 31.16,13.01 28.02,16.15 U402.B1
LD_I2C_SDA: length 16.9
  TOP w0.091: R421.1 41.08,15 40.57,14.5 38.73,14.5 37.48,13.25 31.4,13.25 30.31,14.34 R434.1 29.92,14.95 28.31,16.55 U402.C1
LD_NFLT: length 10.3
  TOP w0.091: v1(31.65,16.35) 31.65,16.24 31.43,16.02 R1776.1 ; U401.11 v1(37.72,19.59) 37.72,19.9 R1775.2
  BOTTOM w0.091: v1(37.72,19.59) 36.2,18.07 33.59,18.07 31.87,16.35 v1(31.65,16.35)
LD_NINT: length 3.2
  TOP w0.091: U402.D1 28.22,16.95 29.15,16.02 R1776.2
LED_B: length 3.2
  TOP w0.091: Q1401.3 79.15,84 R1424.2
LED_G: length 1.6
  TOP w0.091: R1423.2 82.21,73.83 83.17,72.86 Q1402.3
LED_R: length 2.1
  TOP w0.091: R1425.2 80.75,73.95 Q1403.3
LPD4/X_VDD2_1V1: length 28.3
  TOP w0.127: U701.52 64.11,35.13 64.07,35.17 v1(64.07,35.21)
  TOP w0.203: U101.P4 v1(85.99,50.71) ; U101.N6 v1(86.49,50.71) ; U101.M5 v1(86.49,51.71) ; U101.K5 v1(86.49,52.7)
  TOP w0.254: U201.N3 70.23,54.08 v1(69.88,54.43) ; U201.K3 71.92,54.26 71.92,54.37 v1(71.83,54.46) ; v1(64.05,53.61) 64.38,53.28 U201.AB4 ; U201.N1 70.23,55.68 v1(69.81,56.1) ; v1(73.8,52.83) 73.8,52.73 U201.H5 ; U201.R8 68.93,49.93 v1(68.6,49.6) ; v1(69.87,48.79) 69.92,48.79 70.23,48.48 U201.N10 ; U201.R12 68.93,46.73 v1(68.6,46.4) ; U201.R5 68.93,52.17 v1(69.14,51.95) ; U201.H8 73.48,50.39 v1(73.52,50.44) ; v1(73.48,56.16) 73.48,55.9 U201.H1 ; v1(69.9,46.4) 70.23,46.73 U201.N12 ; v1(74.48,49.62) 74.48,49.7 U201.F8 ; U201.U8 67.63,49.93 v1(67.3,49.6) ; v1(68.93,56.04) U201.R1 ; U201.K12 v1(71.75,46.38) ; v1(74.48,52.77) 74.48,52.71 U201.F5 ; U201.H12 73.48,46.76 v1(73.13,46.41) ; U201.A9 78.5,49.21 v1(78.51,49.2) ; U201.A4 v1(78.5,53.21) ; U201.AB9 64.38,49.13 v1(64.05,48.8) ; v1(67.3,52.81) 67.63,52.48 U201.U5 ; v1(71.8,55.94) 71.84,55.94 U201.K1 ; U201.K10 v1(71.78,48.01)
  BOTTOM w0.203: v1(64.07,35.21) 64.07,39.01 v1(62.2,40.88)
  BOTTOM w0.254: v1(69.14,51.95) 68.9,51.95 C210.1 ; v1(71.78,48.01) 71.65,47.88 C211.1 ; v1(69.81,56.1) 69.78,56.13 C207.1 ; v1(78.51,49.2) 78.66,49.05 C208.1 ; C213.1 68.54,49.67 v1(68.6,49.6) ; v1(86.49,52.7) 86.47,52.72 C138.1 ; v1(73.48,56.16) 73.48,55.92 73.73,55.67 R210.1 ; v1(78.5,53.21) 78.65,53.35 C214.1 ; v1(69.9,46.4) 69.88,46.37 C212.1 ; v1(69.88,54.43) 69.92,54.39 C206.1
  vias: v1(60.63,42.75) v1(60.64,42.12) v1(61.27,42.74) v1(61.28,42.14) v1(61.9,42.74) v1(61.92,42.14)
LPD4/X_VDDQ_0V6: length 20.7
  TOP w0.203: U101.F5 v1(86.49,54.7) ; U101.H5 v1(86.49,53.7)
  TOP w0.254: v1(64.72,47.99) 64.72,48.09 U201.AA10 ; U201.W8 66.33,49.93 v1(65.99,49.59) ; U201.B10 77.38,48.53 77.13,48.78 v1(77.04,48.78) ; v1(77.7,52.05) 77.7,52.09 U201.B5 ; v1(75.09,48.83) 75.09,48.71 U201.F10 ; U201.B8 77.6,50.22 77.6,50.31 v1(77.65,50.36) ; v1(77.06,53.65) 77.06,53.69 U201.B3 ; U201.W12 66.06,46.54 v1(66.06,46.36) ; U201.U3 67.63,54.05 v1(67.3,54.38) ; v1(67.33,48.01) 67.33,48.1 U201.U10 ; v1(66,52.79) 66.33,52.46 U201.W5 ; U201.AA5 65.03,52.42 64.74,52.72 v1(64.74,52.8) ; U201.D5 76.08,52.29 v1(76.37,51.99) ; U201.AA8 64.7,49.68 v1(64.7,49.6) ; v1(64.75,54.39) 65.03,54.11 U201.AA3 ; v1(76.42,55.21) 76.42,55.26 U201.D1 ; U201.D8 76.08,50.15 76.33,50.4 v1(76.36,50.4) ; U201.D12 76.41,47.14 v1(76.41,47.22) ; v1(66,55.99) 66.33,55.67 U201.W1 ; U201.F3 75.11,53.68 v1(75.11,53.62)
  BOTTOM w0.203: v1(86.49,54.7) 86.69,54.7 C153.1
  BOTTOM w0.254: v1(65.99,49.59) 65.96,49.62 C220.1 ; C215.1 65.95,56.05 v1(66,55.99) ; v1(64.75,54.39) 64.64,54.49 C219.1 ; v1(75.11,53.62) 75.11,54.52 75.81,55.21 v1(76.42,55.21) 76.77,55.21 C218.1 ; v1(75.09,48.83) 75.09,47.85 75.71,47.22 v1(76.41,47.22) 76.69,47.22 C216.1 ; v1(66.06,46.36) 65.97,46.27 C222.1
  vias: v1(64.78,43.12) v1(64.78,42.51) v1(65.35,42.94) v1(66.6,42.84) v1(67.08,43.01) v1(67,42.51)
LPD4X_VDDQ_0V6: length 7.6
  TOP w0.127: U701.44 67.31,34.76 v1(67.53,34.97)
  BOTTOM w0.203: v1(67.53,34.97) 67.53,38.88 v1(69.42,40.77)
LRCLK1: length 3.5
  TOP w0.081: U1709.D3 104.78,27.57 106.15,27.57
  TOP w0.102: R1205.2 106.85,27.15 106.85,27.37 106.65,27.57 106.15,27.57
LS_OE: length 3.5
  TOP w0.254: U906.12 v1(120.06,28.98) 119.33,28.98 R935.2
  BOTTOM w0.254: U905.12 120.06,28.98 v1(120.06,28.98) 119.95,29.08 R1812.2
M2_LED1#: length 4
  TOP w0.091: J1707.6 132.1,14.68 133.46,16.03 D1705.C
M2_LED2#: length 3.5
  TOP w0.091: D1706.C 131.01,16.57 129.6,15.17 J1707.16
M2_NALERT: length 46.4
  TOP w0.091: R818.2 v1(115.76,60.17) ; v1(118.45,38.69) 118.14,38.69 116.17,36.72 116.17,34.04 116.43,33.77 116.43,26.03 116.9,25.56 116.9,20.48 116.53,20.1 R936.2 116.17,19.09 R932.2
  BOTTOM w0.091: v1(115.76,60.17) 115.76,59.34 113.74,57.32 113.74,51.77 116.9,48.6 116.9,43.23 118.45,41.69 v1(118.45,38.69)
M2_NDIS1: length 76.1
  TOP w0.091: J1707.56 119.6,15.69 118.77,16.52 118.77,19.54 118.5,19.82 118.5,20.83 118.32,21.01 118.32,24.45 116.65,26.12 116.65,35.11 116.39,35.38 116.39,36.4 v1(116.63,36.64) 117.43,37.44 120.14,37.44 122.26,35.33 125.32,35.33 127.45,33.2 127.45,30.58 R903.1 ; v1(109.36,67.78) 109,67.42 R835.2
  BOTTOM w0.091: v1(116.63,36.64) 116.52,36.64 116.01,37.15 116.01,40.51 114.29,42.23 114.29,47.9 111.55,50.64 111.55,65.59 v1(109.36,67.78)
M2_NDIS2: length 82.5
  TOP w0.091: v1(131.05,23.04) 131.79,22.3 135.66,22.3 135.89,22.52 Q902.1 135.89,25.41 136.33,25.85 R953.1 ; R832.2 v1(110.01,67.81) ; v1(117,36.2) 117,36.2 116.61,35.8 116.61,35.47 116.87,35.2 116.87,26.21 118.54,24.54 118.54,21.1 118.88,20.77 v1(118.88,20.54) 118.88,20.23 119.03,20.07 119.03,16.97 120.1,15.9 J1707.54
  BOTTOM w0.091: v1(118.88,20.54) 119.19,20.54 119.4,20.75 123.73,20.75 124.62,21.63 129.64,21.63 v1(131.05,23.04) ; v1(117,36.2) 117.21,36.41 117.21,36.59 116.54,37.26 116.54,40.28 114.51,42.32 114.51,47.99 111.77,50.73 111.77,66.05 v1(110.01,67.81)
M2_NRST: length 59
  TOP w0.091: J1707.52 120.6,16.1 119.25,17.46 119.25,20.7 118.76,21.19 118.76,24.79 117.09,26.46 117.09,35.58 v1(117,35.67) ; R833.2 v1(111.03,67.81)
  BOTTOM w0.091: v1(111.03,67.81) 111.99,66.85 111.99,50.82 114.73,48.08 114.73,42.41 116.76,40.37 116.76,37.35 117.43,36.68 117.43,36.09 v1(117,35.67)
M2_PCM_CLK: length 8.6
  TOP w0.091: J1707.8 131.6,15.12 132.53,16.04 132.53,20.19 131.31,21.42 R946.2
M2_PCM_IN: length 11.6
  TOP w0.091: v1(130.07,20.8) 130.25,20.62 131.49,20.62 132.09,20.01 132.09,16.36 130.6,14.87 J1707.12 ; R949.2 128.39,20.99 v1(128.39,20.8)
  BOTTOM w0.091: v1(130.07,20.8) v1(128.39,20.8)
M2_PCM_OUT: length 10.6
  TOP w0.091: J1707.14 130.1,14.68 131.87,16.45 131.87,19.9 131.39,20.39 129.47,20.39 129.05,20.81 R948.2
M2_PCM_SYNC: length 9.5
  TOP w0.091: R947.2 130.53,20.98 131.43,20.98 132.31,20.1 132.31,16.14 131.1,14.93 J1707.10
M2_PWRON: length 6.6
  TOP w0.254: R922.2 129.86,33.01 130.04,33.2 U1710.5 ; R922.2 R950.2 R1781.1 R903.2 ; R922.2 129.11,33.93 C1754.1
M2_SD_NWAKE: length 6.7
  TOP w0.091: 127.99,4.71 128.35,4.71 128.54,4.52 128.54,3.81 128.29,3.56 127.02,3.56 126.76,3.3 125.68,3.3 TP918.1 ; 127.99,4.71 R1793.2 ; 127.99,4.71 128.35,5.07 J1707.21
M2_UART_NWAKE: length 59.4
  TOP w0.091: J1707.20 128.6,16.85 129.53,17.78 R924.2 130.02,17.78 130.11,17.87 130.11,19.26 129.27,20.1 128.18,20.1 127.45,20.83 127.45,23.12 125.47,25.1 125.47,31.67 120.07,37.07 118.5,37.07 117.39,35.96 117.39,35.65 v1(117.8,35.24) ; R809.2 v1(109.14,56.04)
  BOTTOM w0.091: v1(109.14,56.04) 108.83,55.72 108.83,51.97 113.33,47.47 113.33,39.33 115.53,37.13 115.53,35.94 116.41,35.06 117.62,35.06 v1(117.8,35.24)
M2_USB_DN: length 3.2
  TOP w0.091: TP1935.1 133.67,4.7 133.2,5.17 132.74,5.17 132.35,5.56 J1707.5
M2_USB_DP: length 3.7
  TOP w0.091: J1707.3 132.85,5.56 132.99,5.42 133.78,5.42 TP1934.1
M33_NMI: length 1.9
  TOP w0.091: U1702.8 25.57,69.01 TP1701.1
MIC/CAN_SEL: length 100.7
  TOP w0.091: v1(42.29,74.03) 38.37,74.03 35.12,77.28 35.12,77.74 34.62,78.24 31.63,78.24 30.57,79.3 25.39,79.3 v1(25.05,78.96) ; v1(49.21,74.03) 57.78,74.03 61.35,70.47 69.84,70.47 70.28,70.9 89.45,70.9 89.77,70.59 92.05,70.59 93.32,69.32 101.84,69.32 102.37,68.78 107.67,68.78 108.64,67.82 108.87,67.82 109.23,68.18 111.19,68.18 112.05,67.32 R829.2 ; R1706.1 24.06,74 v1(24.26,73.79) 24.77,73.28 U1702.15
  BOTTOM w0.091: v1(24.26,73.79) 24.13,73.93 24.13,78.04 v1(25.05,78.96) ; v1(42.29,74.03) 42.54,73.78 48.96,73.78 v1(49.21,74.03)
MICBIAS: length 12.4
  TOP w0.102: U1709.A4 103.96,26.26 103.96,25.51 106.36,23.1
  TOP w0.203: 106.36,23.1 106.36,22.91 109.03,20.24 C1208.1 109.04,17.56 R1809.1
MX_POR_B: length 36.2
  TOP w0.081: 87.25,56.83 87.25,56.45 U101.B7
  TOP w0.091: TP402.1 85.42,63.85 84.29,63.85 84.08,64.06 C401.1 83.16,64.66 R402.2 ; v1(84.86,70.31) 85.02,70.15 91.86,70.15 94.43,67.58 95.5,67.58 98.37,64.71 R404.2 ; 87.25,56.83 87.34,56.92 87.34,61.98 86.68,62.65 86.68,62.65
  TOP w0.102: 86.68,62.65 86.5,62.83 v1(86.5,63.45) 86.5,63.47 TP402.1
  BOTTOM w0.091: v1(84.86,70.31) 84.86,67.65
  BOTTOM w0.102: 84.86,67.65 84.86,66.7 86.99,64.57 86.99,64.31 86.5,63.82 v1(86.5,63.45)
NVCC_BBSM_1V8: length 156.6
  TOP w0.203: U701.3 61.13,32.35 60.99,32.49 60.39,32.49 60.27,32.37 C727.1 ; v1(89.49,54.71) U101.E10
  TOP w0.254: R703.1 v1(58.2,30.88) ; TP709.1 57.73,33.52 v1(58.41,32.84) 59.57,32.84 59.83,32.59 C727.1
  TOP w0.381: v1(98.83,70.15) 98.73,70.24 92.91,70.24 92.2,70.95 89.92,70.95 89.6,71.27 82.23,71.27 v1(82.15,71.35) ; R1431.1 53.21,76.85 v1(54.52,75.53) 55.64,75.53 R403.1 56.6,76.53 R1432.1 ; R402.1 v1(81.62,64.69) 68.15,64.69 62.97,59.5 v1(55.29,59.5) ; v1(55.86,43.67) 55.78,43.59 52.81,43.59 51.72,44.68 R401.1
  TOP w0.762: v1(59.55,76.1) 59.55,78.25 J1403.2 J1403.1
  L3_PWR w0.381: v1(89.49,54.71) 89.27,54.71 88.99,54.99 88.99,56.03 90.45,57.5 97.64,57.5 v1(98.8,56.34)
  BOTTOM w0.254: C101.1 89.54,54.66 v1(89.49,54.71)
  BOTTOM w0.381: v1(82.15,71.35) 81.62,70.82 v1(81.62,64.69) ; v1(98.83,70.15) 98.83,56.36 v1(98.8,56.34) ; v1(58.2,30.88) 58.31,30.99 58.31,32.75 v1(58.41,32.84) 55.86,35.39 v1(55.86,43.67) 55.29,44.23 v1(55.29,59.5) 55.29,70.56 54.49,71.36 54.49,75.5 v1(54.52,75.53)
  BOTTOM w0.508: v1(54.52,75.53) 55.03,76.03 59.48,76.03 v1(59.55,76.1)
NVCC_SD2: length 119.3
  TOP w0.203: 62.62,34.77 62.91,34.47 U701.55
  TOP w0.254: R1052.1 C1019.1 137.5,42.76 U1707.5 ; U101.N12 v1(90.46,50.71)
  TOP w0.381: v1(59.88,43.23) 59.88,43.3 60.26,43.69 70.48,43.69 v1(71.98,42.18) ; v1(120.09,54.97) 121.36,54.97 121.61,55.21 R311.1 ; U1707.5 v1(136.3,42.01) ; v1(99.38,51.18) 99.46,51.1 116.52,51.1 v1(117.12,51.7) ; v1(59.55,38.76) 59.55,38.17 TP713.1 59.15,37.77 59.15,36.07 59.52,35.7 C731.1 60.42,35.7 61.36,34.77 62.62,34.77
  TOP w0.457: R310.1 v1(122.2,51.83) ; v1(132.47,46.93) 132.18,46.64 130.01,46.64 129.54,46.17 v1(122.29,46.17)
  BOTTOM w0.254: v1(90.46,50.71) 90.22,50.71 90.01,50.5 C129.1 90.01,49.82 89.95,49.76 89.95,49.39 90.19,49.15 R312.1
  BOTTOM w0.381: v1(59.88,43.23) 59.88,39.1 v1(59.55,38.76) ; v1(99.38,51.18) 99.38,49.85 97.98,48.45 94.93,48.45 94.12,49.26 92.06,49.26 91.59,48.79 R312.1 90.19,45.49 88.2,43.5 85.54,43.5 84.23,42.18 v1(71.98,42.18)
  BOTTOM w0.457: v1(117.12,51.7) 117.12,53.14 118.72,54.75
  BOTTOM w0.508: v1(136.3,42.01) 135.52,42.01 132.47,45.06 v1(132.47,46.93) ; 118.72,54.75 118.94,54.97 v1(120.09,54.97) 120.39,54.97 122.2,53.16 v1(122.2,51.83) 122.2,46.26 v1(122.29,46.17)
ODT_CA_A: length 1.2
  TOP w0.081: U201.G2 74.43,55.1 v1(74.43,55.19)
  BOTTOM w0.091: v1(74.43,55.19) 74.15,54.92 R210.2
ONOFF: length 122.6
  TOP w0.081: v1(89.49,55.21) U101.D10
  TOP w0.091: v1(64.81,65.6) 64.74,65.67 64.74,66.04 65.8,67.09 90.04,67.09 91.61,65.52 91.61,61.46 v1(91.56,61.41) ; v1(48.48,75.03) 48.65,74.85 56.92,74.85 v1(57.37,74.41) 57.72,74.41 61.28,70.84 v1(61.61,70.84) ; R1741.2 12.63,63.73 v1(12.99,64.1) ; R403.2 57.37,75.54 v1(57.46,75.45) ; v1(43.28,74.79) 43.22,74.85 38.63,74.85 34.8,78.68 32.03,78.68 30.81,79.9 22.76,79.9 21.97,80.69 C1411.1 21.95,81.22 R1426.2 21.86,82.18 TP401.1 20.44,81.92 14.01,81.92 v1(13.52,82.41)
  BOTTOM w0.091: v1(48.48,75.03) 43.51,75.03 v1(43.28,74.79) ; v1(57.46,75.45) 57.37,75.36 v1(57.37,74.41) ; v1(13.52,82.41) 13.73,82.2 13.73,64.84 v1(12.99,64.1) ; v1(89.49,55.21) 91.56,57.28 v1(91.56,61.41) ; v1(61.61,70.84) 63.66,68.79 63.66,66.76 v1(64.81,65.6)
PCIE_CLKN: length 3.6
  TOP w0.091: J1707.49 121.35,5.4 120.87,4.92 120.5,4.92 119.98,4.4 TP909.1
PCIE_CLKP: length 2.8
  TOP w0.091: J1707.47 121.85,5.56 TP908.1
PCIE_NCLKREQ: length 3.7
  TOP w0.091: J1707.53 120.35,5.56 119.66,4.86 118.71,4.86 TP910.1
PCIE_NWAKE: length 6.1
  TOP w0.091: v1(119.85,8.02) J1707.55 119.85,5.76 119.34,5.24 117.68,5.24 TP920.1
  BOTTOM w0.381: R917.2 119.87,8.03 v1(119.85,8.02)
PCIE_RXN: length 2.7
  TOP w0.091: TP907.1 122.85,5.28 J1707.43
PCIE_RXP: length 2.4
  TOP w0.091: J1707.41 123.35,4.94 123.19,4.77 TP906.1
PCIE_TXN: length 2.3
  TOP w0.091: TP905.1 124.41,4.77 124.35,4.83 J1707.37
PCIE_TXP: length 2.6
  TOP w0.091: J1707.35 124.85,5.14 TP911.1
PD_BYPASS: length 1.3
  TOP w0.091: C306.2 67.84,15.13 U301.4
PD_DBG_ACC: length 2
  TOP w0.091: U301.9 66.58,11.99 TP308.1
PD_EN_SINK: length 3
  TOP w0.091: U301.2 68.64,14.93 69.85,16.14 69.85,16.36 R1760.1
PD_EN_SRC: length 1.5
  TOP w0.091: U301.16 70.32,13.64 TP306.1
PD_FRS_EN: length 2.5
  TOP w0.091: TP307.1 69.96,15.77 69.04,14.85 U301.1
PD_ILIM_5V_VBUS: length 1.5
  TOP w0.091: TP309.1 66.59,13.64 U301.6
PD_LD_NFLT: length 1.6
  TOP w0.091: R1764.1 68.24,10.65 U301.11
PD_USB_CC1: length 9.9
  TOP w0.091: U303.A2 72.01,8.3 71.3,7.59 70.36,7.59 70.27,7.68 70.27,11.3 69.58,11.99 U301.13
PD_USB_CC2: length 5.8
  TOP w0.091: U301.14 72.67,12.84 73.13,12.38 73.13,11.97 72.92,11.76 U303.C1 U303.C2 U303.B2
PD_USB_VBUS_IN: length 2.2
  TOP w0.254: TP302.1 46.65,20.97 R302.1
PD_VBUS_PG: length 12.4
  TOP w0.254: Q302.1 53.75,21.76 R1763.2 54.12,21.7 54.49,21.33 54.49,20.57 53.81,19.9 48.42,19.9 47.79,20.53 TP304.1 47.44,21.37 U302.A2
PDM_CLK: length 97.4
  TOP w0.091: R1703.1 21.6,72.19 21.6,77.94 23.18,79.52 30.88,79.52 31.94,78.46 34.71,78.46 38.7,74.48 43.05,74.48 v1(43.27,74.26) ; v1(55.57,74.48) 48.68,74.48 v1(48.53,74.33) ; v1(55.54,71.78) 57.87,71.78 60.71,68.94 69.56,68.94 69.87,68.62 91.23,68.62 94.46,65.39 94.46,61.94 v1(94.54,61.86) ; v1(92.37,58.37) 91.99,58 U101.A16
  BOTTOM w0.081: 92.59,58.37 92.54,58.32 92.42,58.32 v1(92.37,58.37)
  BOTTOM w0.091: v1(55.57,74.48) 55.54,74.44 v1(55.54,71.78) ; v1(94.54,61.86) 94.21,61.86 92.68,60.32 92.68,58.46 92.59,58.37 ; v1(48.53,74.33) 48.46,74.26 v1(43.27,74.26)
PDM_DATA0: length 82.9
  TOP w0.091: R1704.1 23.7,67.77 24.5,67.77 26.57,65.69 32.07,65.69 37.92,59.84 46.11,59.84 47.4,61.12 61.76,61.12 66.86,66.22 89.67,66.22 90.14,65.75 90.14,62.3 89.21,61.37 89.21,59.3 89.06,59.14 89.06,56.77 U101.A10
PDM_DATA1: length 82.6
  TOP w0.081: 89.28,58.37 89.28,57.43 89.25,57.4 89.25,56.46 U101.B10
  TOP w0.091: 89.28,58.37 89.28,58.94 89.43,59.09 89.43,61.28 90.36,62.21 90.36,65.84 89.76,66.44 66.77,66.44 61.84,61.51 47.41,61.51 46,60.1 38.03,60.1 32.22,65.91 26.66,65.91 R1705.1
PMIC_32K_OUT: length 160.2
  TOP w0.091: R958.2 121.3,21.86 v1(121.3,21.12) ; 60.53,30.75 59.84,31.44 55.95,31.44 v1(54.93,30.42) ; v1(87.18,63.81) 87.18,64.39 86.45,65.11 67.78,65.11 62.64,59.98 52.46,59.98 v1(51.67,59.18)
  TOP w0.104: 60.53,30.75 U701.7
  BOTTOM w0.091: v1(51.67,59.18) 51.67,33.68 v1(54.93,30.42) 54.94,30.41 54.94,19.35 55.86,18.43 63.85,18.43 67.02,21.6 67.33,21.6 67.63,21.3 67.63,20.43 68.76,19.31 73.54,19.31 74.62,20.39 117.14,20.39 117.74,20.98 119.07,20.98 119.22,21.12 v1(121.3,21.12)
  BOTTOM w0.102: R406.1 86.98,63.61 v1(87.18,63.81)
PMIC_NINT: length 118.1
  TOP w0.091: v1(55.9,23.5) 56.13,23.72 59.05,23.72 59.15,23.82 59.15,24.55 59.97,25.38 59.97,26.79 60.69,27.51 60.69,27.89 61.15,28.35 U701.13 ; R822.2 115.24,61.09 v1(115.82,61.09) R817.2
  BOTTOM w0.091: v1(55.9,23.5) 55.52,23.12 55.52,19.38 56.04,18.87 63.52,18.87 66.87,22.22 68.09,22.22 68.25,22.06 69.5,22.06 70.11,22.67 74.11,22.67 74.55,23.11 75.58,23.11 76.01,22.67 76.99,22.67 77,22.67 91.56,22.67 101.97,33.09 109.49,33.09 110,33.6 120.09,33.6 120.9,34.41 120.9,35.51 118.98,37.43 118.98,41.73 117.26,43.45 117.26,48.55 113.96,51.86 113.96,57.23 116.19,59.46 116.19,60.72 v1(115.82,61.09)
PMIC_ON_REQ: length 151
  TOP w0.091: R707.1 73.61,36.99 73.61,43.03 71.93,44.71 54.22,44.71 52.19,46.74 v1(51.19,46.74) 49.79,46.74 48.14,45.09 ; v1(34.79,39.4) 34.79,44.17 35.86,45.24 47.98,45.24 48.14,45.09 ; Q1409.1 v1(19.05,19.85) ; 48.14,45.09 48.14,44.49 48.72,43.91 R418.1 50.93,43.91 R401.2 51.56,43.94 TP403.1 52.07,43.42 R915.1 ; v1(32.87,39.4) 32.85,39.41 29.83,39.41 27.31,36.9 27.31,34.33 25.79,32.8 v1(22.53,32.8) ; v1(51.19,59.56) 51.98,60.35 62.71,60.35 67.69,65.33 86.54,65.33 87.56,64.32 87.56,56.77 U101.A7
  BOTTOM w0.091: v1(19.05,19.85) 20.58,21.39 20.58,30.85 v1(22.53,32.8) ; v1(34.79,39.4) v1(32.87,39.4) ; v1(51.19,46.74) v1(51.19,59.56)
PMIC_STBY_REQ: length 153.8
  TOP w0.081: U101.C9 88.75,55.96 88.75,56.81 88.84,56.9 88.84,58.37
  TOP w0.091: 88.84,58.37 88.84,59.84 88.48,60.2 88.48,63.62 R424.1 88.99,64.52 89.24,64.77 89.24,65.45 TP404.1 88.71,65.99 66.94,65.99 61.67,60.72 v1(54.32,60.72) 47.74,60.72 46.64,59.62 37.83,59.62 34.68,62.78 v1(34.46,62.78) ; v1(32.52,57.09) 32.52,56.67 32.41,56.56 26.51,56.56 23.55,53.6 23.55,51.44 22.01,49.9 18.1,49.9 15.9,52.09 15.9,53.87 12.54,57.23 10.59,57.23 10.05,56.69 8.32,56.69 7.81,57.2 Q1410.1 ; R708.1 73.4,37.83 73.4,42.54 71.44,44.49 53.91,44.49 v1(53.36,45.04)
  BOTTOM w0.091: v1(54.32,60.72) 54.32,60.42 52.5,58.6 52.5,45.9 v1(53.36,45.04) ; v1(34.46,62.78) 33.28,61.6 33.28,57.84 v1(32.52,57.09)
